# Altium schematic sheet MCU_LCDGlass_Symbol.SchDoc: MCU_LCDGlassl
size A3; DocumentNumber: MB1144; Revision: C-02; SheetNumber: 2; SheetTotal: 25; PageSetup: Record=PageOptions|CenterHorizontal=True|CenterVertical=True|PrintScale=1.01|XCorrection=1.00|YCorrection=1.00|PrintKind=1|BorderSize=5000000|LeftOffset=0|BottomOffset=0|Orientation=2|PaperLength=1000|PaperWidth=1000|Scale=100|PaperSource=264|PrintQuality=600|MediaType=1|DitherType=10|PaperKind=A3|PrintScaleMode=1; Project: STM32L476G-EVAL
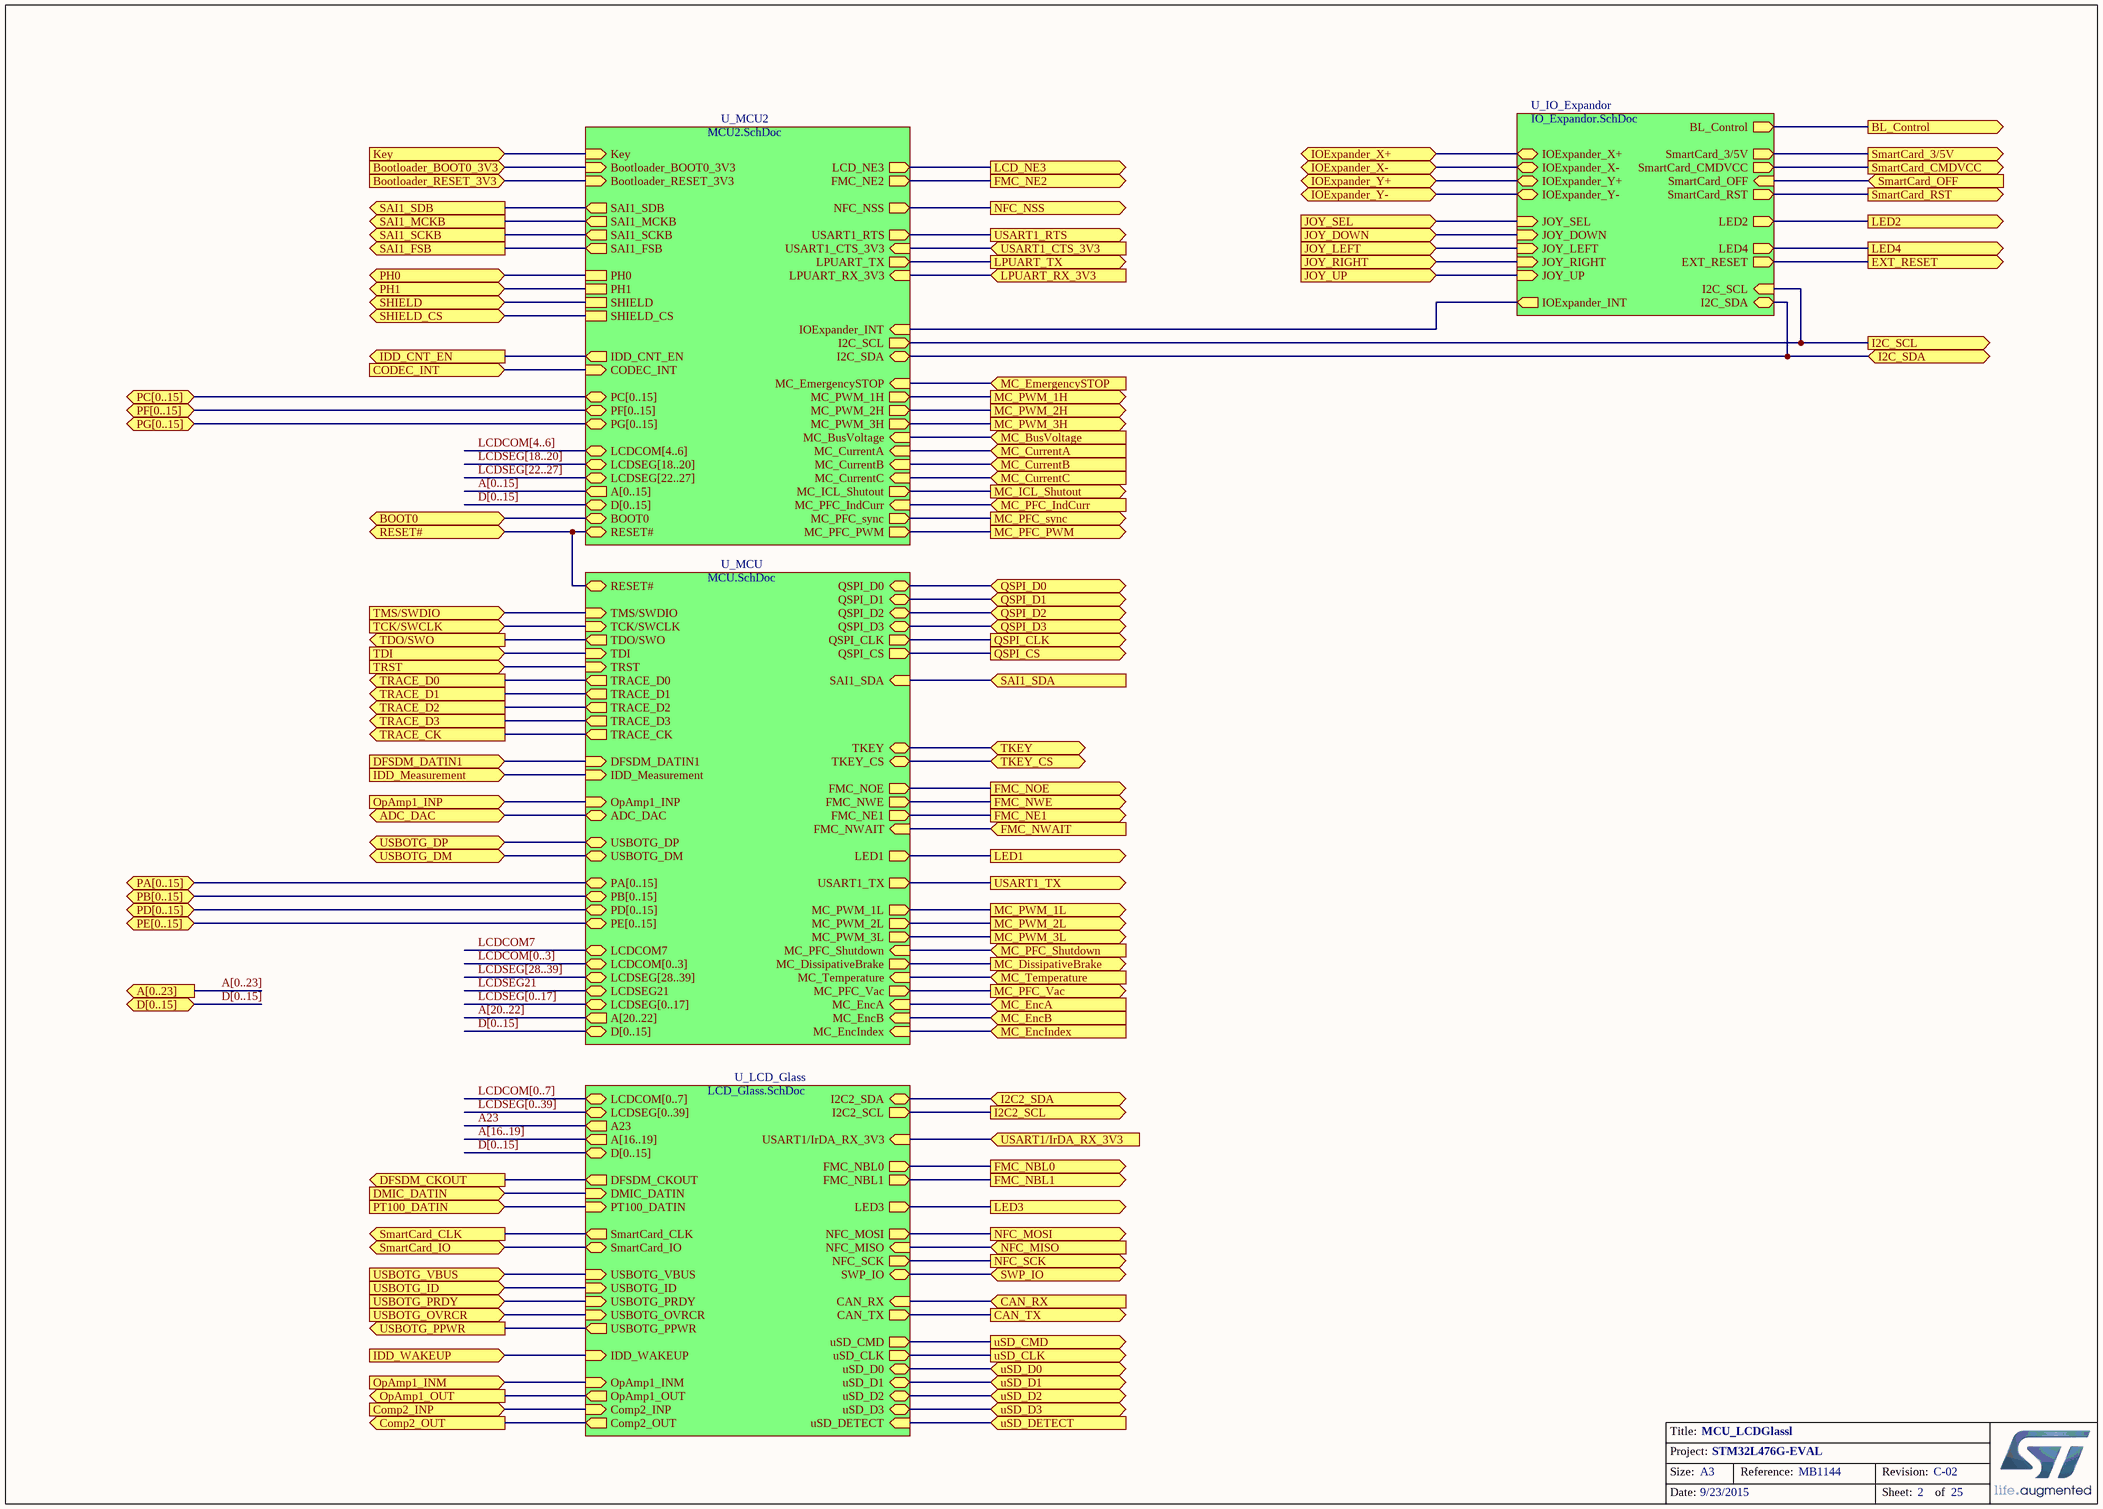
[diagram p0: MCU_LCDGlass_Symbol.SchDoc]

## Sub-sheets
U_IO_Expandor = IO_Expandor.SchDoc: IOExpander_Y+ (bidir), IOExpander_Y- (bidir), IOExpander_X+ (bidir), IOExpander_X- (bidir), IOExpander_INT (out), I2C_SDA (bidir), JOY_SEL (in), JOY_DOWN (in), JOY_LEFT (in), JOY_RIGHT (in), JOY_UP (in), LED4 (out), SmartCard_RST (out), SmartCard_CMDVCC (out), SmartCard_3/5V (out), SmartCard_OFF (in), I2C_SCL (in), LED2 (out), BL_Control (out), EXT_RESET (out)
U_LCD_Glass = LCD_Glass.SchDoc: uSD_CMD (out), uSD_CLK (out), uSD_D3 (bidir), uSD_D2 (bidir), IDD_WAKEUP (in), PT100_DATIN (in), uSD_D0 (bidir), uSD_D1 (bidir), OpAmp1_INM (in), FMC_NBL0 (out), FMC_NBL1 (out), LCDSEG[0..39] (bidir), LCDCOM[0..7] (bidir), USBOTG_VBUS (in), USBOTG_ID (in), CAN_TX (out), SWP_IO (bidir), CAN_RX (in), DMIC_DATIN (in), OpAmp1_OUT (out), Comp2_INP (in), SmartCard_CLK (out), SmartCard_IO (bidir), uSD_DETECT (in), DFSDM_CKOUT (out), D[0..15] (bidir), USBOTG_PRDY (in), USBOTG_OVRCR (in), USBOTG_PPWR (out), Comp2_OUT (out), USART1/IrDA_RX_3V3 (in), A[16..19] (out), A23 (out), NFC_MISO (in), NFC_SCK (out), NFC_MOSI (out), I2C2_SDA (bidir), I2C2_SCL (out), LED3 (out)
U_MCU = MCU.SchDoc: PA[0..15] (bidir), PB[0..15] (bidir), PD[0..15] (bidir), PE[0..15] (bidir), USBOTG_DM (bidir), USBOTG_DP (bidir), TMS/SWDIO (in), TCK/SWCLK (in), DFSDM_DATIN1 (in), FMC_NOE (out), FMC_NWE (out), FMC_NWAIT (in), FMC_NE1 (out), TRACE_D3 (out), TRACE_D1 (out), TRST (in), D[0..15] (bidir), IDD_Measurement (in), USART1_TX (out), LED1 (out), MC_DissipativeBrake (out), TRACE_D2 (out), MC_EncA (in), TDI (in), TDO/SWO (out), ADC_DAC (bidir), RESET# (bidir), QSPI_D3 (bidir), QSPI_D2 (bidir), QSPI_D1 (bidir), QSPI_D0 (bidir), QSPI_CLK (out), QSPI_CS (out), TRACE_D0 (out), TRACE_CK (out), SAI1_SDA (in), OpAmp1_INP (in), MC_PFC_Vac (out), MC_Temperature (in), MC_EncB (in), MC_EncIndex (in), TKEY, TKEY_CS, MC_PWM_1L (out), MC_PWM_2L (out), MC_PWM_3L (out), MC_PFC_Shutdown (in), A[20..22] (out), LCDCOM[0..3] (bidir), LCDCOM7, LCDSEG[0..17] (bidir), LCDSEG[28..39] (bidir), LCDSEG21 (bidir)
U_MCU2 = MCU2.SchDoc: PC[0..15] (bidir), Bootloader_BOOT0_3V3 (in), Bootloader_RESET_3V3 (in), Key (in), CODEC_INT (in), USART1_CTS_3V3 (in), FMC_NE2 (out), USART1_RTS (out), PF[0..15] (bidir), PG[0..15] (bidir), D[0..15] (bidir), MC_PFC_sync (out), IDD_CNT_EN (out), LPUART_TX (out), LPUART_RX_3V3 (in), LCD_NE3 (out), IOExpander_INT (in), I2C_SCL (out), I2C_SDA (bidir), RESET# (bidir), PH1, PH0, SHIELD, SAI1_SDB (out), SAI1_MCKB (out), SAI1_SCKB (out), SAI1_FSB (out), MC_ICL_Shutout (out), MC_PFC_PWM (out), MC_CurrentB (in), MC_CurrentC (in), MC_CurrentA (in), MC_PFC_IndCurr (in), MC_BusVoltage (in), MC_PWM_1H (out), SHIELD_CS, MC_PWM_2H (out), MC_PWM_3H (out), MC_EmergencySTOP (in), A[0..15] (out), LCDSEG[18..20] (bidir), LCDCOM[4..6] (bidir), LCDSEG[22..27] (bidir), BOOT0, NFC_NSS (out)

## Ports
A[0..23] (out), ADC_DAC (bidir), BL_Control (out), BOOT0, Bootloader_BOOT0_3V3 (in), Bootloader_RESET_3V3 (in), CAN_RX (in), CAN_TX (out), CODEC_INT (in), Comp2_INP (in), Comp2_OUT (out), D[0..15] (bidir), DFSDM_CKOUT (out), DFSDM_DATIN1 (in), DMIC_DATIN (in), EXT_RESET (out), FMC_NBL0 (out), FMC_NBL1 (out), FMC_NE1 (out), FMC_NE2 (out), FMC_NOE (out), FMC_NWAIT (in), FMC_NWE (out), I2C2_SCL (out), I2C2_SDA (bidir), I2C_SCL (out), I2C_SDA (bidir), IDD_CNT_EN (out), IDD_Measurement (in), IDD_WAKEUP (in), IOExpander_X+ (bidir), IOExpander_X- (bidir), IOExpander_Y+ (bidir), IOExpander_Y- (bidir), JOY_DOWN (in), JOY_LEFT (in), JOY_RIGHT (in), JOY_SEL (in), JOY_UP (in), Key (in), LCD_NE3 (out), LED1 (out), LED2 (out), LED3 (out), LED4 (out), LPUART_RX_3V3 (in), LPUART_TX (out), MC_BusVoltage (in), MC_CurrentA (in), MC_CurrentB (in), MC_CurrentC (in), MC_DissipativeBrake (out), MC_EmergencySTOP (in), MC_EncA (in), MC_EncB (in), MC_EncIndex (in), MC_ICL_Shutout (out), MC_PFC_IndCurr (in), MC_PFC_PWM (out), MC_PFC_Shutdown (in), MC_PFC_sync (out), MC_PFC_Vac (out), MC_PWM_1H (out), MC_PWM_1L (out), MC_PWM_2H (out), MC_PWM_2L (out), MC_PWM_3H (out), MC_PWM_3L (out), MC_Temperature (in), NFC_MISO (in), NFC_MOSI (out), NFC_NSS (out), NFC_SCK (out), OpAmp1_INM (in), OpAmp1_INP (in), OpAmp1_OUT (out), PA[0..15] (bidir), PB[0..15] (bidir), PC[0..15] (bidir), PD[0..15] (bidir), PE[0..15] (bidir), PF[0..15] (bidir), PG[0..15] (bidir), PH0, PH1, PT100_DATIN (in), QSPI_CLK (out), QSPI_CS (out), QSPI_D0 (bidir), QSPI_D1 (bidir), QSPI_D2 (bidir), QSPI_D3 (bidir), RESET# (bidir), SAI1_FSB (out), SAI1_MCKB (out), SAI1_SCKB (out), SAI1_SDA (in), SAI1_SDB (out), SHIELD, SHIELD_CS, SmartCard_3/5V (out), SmartCard_CLK (out), SmartCard_CMDVCC (out), SmartCard_IO (bidir), SmartCard_OFF (in), SmartCard_RST (out), SWP_IO (bidir), TCK/SWCLK (in), TDI (in), TDO/SWO (out), TKEY, TKEY_CS, TMS/SWDIO (in), TRACE_CK (out), TRACE_D0 (out), TRACE_D1 (out), TRACE_D2 (out), TRACE_D3 (out), TRST (in), USART1/IrDA_RX_3V3 (in), USART1_CTS_3V3 (in), USART1_RTS (out), USART1_TX (out), USBOTG_DM (bidir), USBOTG_DP (bidir), USBOTG_ID (in), USBOTG_OVRCR (in), USBOTG_PPWR (out), USBOTG_PRDY (in), USBOTG_VBUS (in), uSD_CLK (out), uSD_CMD (out), uSD_D0 (bidir), uSD_D1 (bidir), uSD_D2 (bidir), uSD_D3 (bidir), uSD_DETECT (in)

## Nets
ADC_DAC: port ADC_DAC, sheet U_MCU/ADC_DAC
BL_Control: port BL_Control, sheet U_IO_Expandor/BL_Control
BOOT0: port BOOT0, sheet U_MCU2/BOOT0
Bootloader_BOOT0_3V3: port Bootloader_BOOT0_3V3, sheet U_MCU2/Bootloader_BOOT0_3V3
Bootloader_RESET_3V3: port Bootloader_RESET_3V3, sheet U_MCU2/Bootloader_RESET_3V3
CAN_RX: port CAN_RX, sheet U_LCD_Glass/CAN_RX
CAN_TX: port CAN_TX, sheet U_LCD_Glass/CAN_TX
CODEC_INT: port CODEC_INT, sheet U_MCU2/CODEC_INT
Comp2_INP: port Comp2_INP, sheet U_LCD_Glass/Comp2_INP
Comp2_OUT: port Comp2_OUT, sheet U_LCD_Glass/Comp2_OUT
DFSDM_CKOUT: port DFSDM_CKOUT, sheet U_LCD_Glass/DFSDM_CKOUT
DFSDM_DATIN1: port DFSDM_DATIN1, sheet U_MCU/DFSDM_DATIN1
DMIC_DATIN: port DMIC_DATIN, sheet U_LCD_Glass/DMIC_DATIN
EXT_RESET: port EXT_RESET, sheet U_IO_Expandor/EXT_RESET
FMC_NBL0: port FMC_NBL0, sheet U_LCD_Glass/FMC_NBL0
FMC_NBL1: port FMC_NBL1, sheet U_LCD_Glass/FMC_NBL1
FMC_NE1: port FMC_NE1, sheet U_MCU/FMC_NE1
FMC_NE2: port FMC_NE2, sheet U_MCU2/FMC_NE2
FMC_NOE: port FMC_NOE, sheet U_MCU/FMC_NOE
FMC_NWAIT: port FMC_NWAIT, sheet U_MCU/FMC_NWAIT
FMC_NWE: port FMC_NWE, sheet U_MCU/FMC_NWE
I2C2_SCL: port I2C2_SCL, sheet U_LCD_Glass/I2C2_SCL
I2C2_SDA: port I2C2_SDA, sheet U_LCD_Glass/I2C2_SDA
I2C_SCL: port I2C_SCL, sheet U_IO_Expandor/I2C_SCL, sheet U_MCU2/I2C_SCL
I2C_SDA: port I2C_SDA, sheet U_IO_Expandor/I2C_SDA, sheet U_MCU2/I2C_SDA
IDD_CNT_EN: port IDD_CNT_EN, sheet U_MCU2/IDD_CNT_EN
IDD_Measurement: port IDD_Measurement, sheet U_MCU/IDD_Measurement
IDD_WAKEUP: port IDD_WAKEUP, sheet U_LCD_Glass/IDD_WAKEUP
IOExpander_X+: port IOExpander_X+, sheet U_IO_Expandor/IOExpander_X+
IOExpander_X-: port IOExpander_X-, sheet U_IO_Expandor/IOExpander_X-
IOExpander_Y+: port IOExpander_Y+, sheet U_IO_Expandor/IOExpander_Y+
IOExpander_Y-: port IOExpander_Y-, sheet U_IO_Expandor/IOExpander_Y-
JOY_DOWN: port JOY_DOWN, sheet U_IO_Expandor/JOY_DOWN
JOY_LEFT: port JOY_LEFT, sheet U_IO_Expandor/JOY_LEFT
JOY_RIGHT: port JOY_RIGHT, sheet U_IO_Expandor/JOY_RIGHT
JOY_SEL: port JOY_SEL, sheet U_IO_Expandor/JOY_SEL
JOY_UP: port JOY_UP, sheet U_IO_Expandor/JOY_UP
Key: port Key, sheet U_MCU2/Key
LCD_NE3: port LCD_NE3, sheet U_MCU2/LCD_NE3
LED1: port LED1, sheet U_MCU/LED1
LED2: port LED2, sheet U_IO_Expandor/LED2
LED3: port LED3, sheet U_LCD_Glass/LED3
LED4: port LED4, sheet U_IO_Expandor/LED4
LPUART_RX_3V3: port LPUART_RX_3V3, sheet U_MCU2/LPUART_RX_3V3
LPUART_TX: port LPUART_TX, sheet U_MCU2/LPUART_TX
MC_BusVoltage: port MC_BusVoltage, sheet U_MCU2/MC_BusVoltage
MC_CurrentA: port MC_CurrentA, sheet U_MCU2/MC_CurrentA
MC_CurrentB: port MC_CurrentB, sheet U_MCU2/MC_CurrentB
MC_CurrentC: port MC_CurrentC, sheet U_MCU2/MC_CurrentC
MC_DissipativeBrake: port MC_DissipativeBrake, sheet U_MCU/MC_DissipativeBrake
MC_EmergencySTOP: port MC_EmergencySTOP, sheet U_MCU2/MC_EmergencySTOP
MC_EncA: port MC_EncA, sheet U_MCU/MC_EncA
MC_EncB: port MC_EncB, sheet U_MCU/MC_EncB
MC_EncIndex: port MC_EncIndex, sheet U_MCU/MC_EncIndex
MC_ICL_Shutout: port MC_ICL_Shutout, sheet U_MCU2/MC_ICL_Shutout
MC_PFC_IndCurr: port MC_PFC_IndCurr, sheet U_MCU2/MC_PFC_IndCurr
MC_PFC_PWM: port MC_PFC_PWM, sheet U_MCU2/MC_PFC_PWM
MC_PFC_Shutdown: port MC_PFC_Shutdown, sheet U_MCU/MC_PFC_Shutdown
MC_PFC_sync: port MC_PFC_sync, sheet U_MCU2/MC_PFC_sync
MC_PFC_Vac: port MC_PFC_Vac, sheet U_MCU/MC_PFC_Vac
MC_PWM_1H: port MC_PWM_1H, sheet U_MCU2/MC_PWM_1H
MC_PWM_1L: port MC_PWM_1L, sheet U_MCU/MC_PWM_1L
MC_PWM_2H: port MC_PWM_2H, sheet U_MCU2/MC_PWM_2H
MC_PWM_2L: port MC_PWM_2L, sheet U_MCU/MC_PWM_2L
MC_PWM_3H: port MC_PWM_3H, sheet U_MCU2/MC_PWM_3H
MC_PWM_3L: port MC_PWM_3L, sheet U_MCU/MC_PWM_3L
MC_Temperature: port MC_Temperature, sheet U_MCU/MC_Temperature
NFC_MISO: port NFC_MISO, sheet U_LCD_Glass/NFC_MISO
NFC_MOSI: port NFC_MOSI, sheet U_LCD_Glass/NFC_MOSI
NFC_NSS: port NFC_NSS, sheet U_MCU2/NFC_NSS
NFC_SCK: port NFC_SCK, sheet U_LCD_Glass/NFC_SCK
OpAmp1_INM: port OpAmp1_INM, sheet U_LCD_Glass/OpAmp1_INM
OpAmp1_INP: port OpAmp1_INP, sheet U_MCU/OpAmp1_INP
OpAmp1_OUT: port OpAmp1_OUT, sheet U_LCD_Glass/OpAmp1_OUT
PH0: port PH0, sheet U_MCU2/PH0
PH1: port PH1, sheet U_MCU2/PH1
PT100_DATIN: port PT100_DATIN, sheet U_LCD_Glass/PT100_DATIN
QSPI_CLK: port QSPI_CLK, sheet U_MCU/QSPI_CLK
QSPI_CS: port QSPI_CS, sheet U_MCU/QSPI_CS
QSPI_D0: port QSPI_D0, sheet U_MCU/QSPI_D0
QSPI_D1: port QSPI_D1, sheet U_MCU/QSPI_D1
QSPI_D2: port QSPI_D2, sheet U_MCU/QSPI_D2
QSPI_D3: port QSPI_D3, sheet U_MCU/QSPI_D3
RESET#: port RESET#, sheet U_MCU/RESET#, sheet U_MCU2/RESET#
SAI1_FSB: port SAI1_FSB, sheet U_MCU2/SAI1_FSB
SAI1_MCKB: port SAI1_MCKB, sheet U_MCU2/SAI1_MCKB
SAI1_SCKB: port SAI1_SCKB, sheet U_MCU2/SAI1_SCKB
SAI1_SDA: port SAI1_SDA, sheet U_MCU/SAI1_SDA
SAI1_SDB: port SAI1_SDB, sheet U_MCU2/SAI1_SDB
SHIELD: port SHIELD, sheet U_MCU2/SHIELD
SHIELD_CS: port SHIELD_CS, sheet U_MCU2/SHIELD_CS
SmartCard_3/5V: port SmartCard_3/5V, sheet U_IO_Expandor/SmartCard_3/5V
SmartCard_CLK: port SmartCard_CLK, sheet U_LCD_Glass/SmartCard_CLK
SmartCard_CMDVCC: port SmartCard_CMDVCC, sheet U_IO_Expandor/SmartCard_CMDVCC
SmartCard_IO: port SmartCard_IO, sheet U_LCD_Glass/SmartCard_IO
SmartCard_OFF: port SmartCard_OFF, sheet U_IO_Expandor/SmartCard_OFF
SmartCard_RST: port SmartCard_RST, sheet U_IO_Expandor/SmartCard_RST
SWP_IO: port SWP_IO, sheet U_LCD_Glass/SWP_IO
TCK/SWCLK: port TCK/SWCLK, sheet U_MCU/TCK/SWCLK
TDI: port TDI, sheet U_MCU/TDI
TDO/SWO: port TDO/SWO, sheet U_MCU/TDO/SWO
TKEY: port TKEY, sheet U_MCU/TKEY
TKEY_CS: port TKEY_CS, sheet U_MCU/TKEY_CS
TMS/SWDIO: port TMS/SWDIO, sheet U_MCU/TMS/SWDIO
TRACE_CK: port TRACE_CK, sheet U_MCU/TRACE_CK
TRACE_D0: port TRACE_D0, sheet U_MCU/TRACE_D0
TRACE_D1: port TRACE_D1, sheet U_MCU/TRACE_D1
TRACE_D2: port TRACE_D2, sheet U_MCU/TRACE_D2
TRACE_D3: port TRACE_D3, sheet U_MCU/TRACE_D3
TRST: port TRST, sheet U_MCU/TRST
USART1/IrDA_RX_3V3: port USART1/IrDA_RX_3V3, sheet U_LCD_Glass/USART1/IrDA_RX_3V3
USART1_CTS_3V3: port USART1_CTS_3V3, sheet U_MCU2/USART1_CTS_3V3
USART1_RTS: port USART1_RTS, sheet U_MCU2/USART1_RTS
USART1_TX: port USART1_TX, sheet U_MCU/USART1_TX
USBOTG_DM: port USBOTG_DM, sheet U_MCU/USBOTG_DM
USBOTG_DP: port USBOTG_DP, sheet U_MCU/USBOTG_DP
USBOTG_ID: port USBOTG_ID, sheet U_LCD_Glass/USBOTG_ID
USBOTG_OVRCR: port USBOTG_OVRCR, sheet U_LCD_Glass/USBOTG_OVRCR
USBOTG_PPWR: port USBOTG_PPWR, sheet U_LCD_Glass/USBOTG_PPWR
USBOTG_PRDY: port USBOTG_PRDY, sheet U_LCD_Glass/USBOTG_PRDY
USBOTG_VBUS: port USBOTG_VBUS, sheet U_LCD_Glass/USBOTG_VBUS
uSD_CLK: port uSD_CLK, sheet U_LCD_Glass/uSD_CLK
uSD_CMD: port uSD_CMD, sheet U_LCD_Glass/uSD_CMD
uSD_D0: port uSD_D0, sheet U_LCD_Glass/uSD_D0
uSD_D1: port uSD_D1, sheet U_LCD_Glass/uSD_D1
uSD_D2: port uSD_D2, sheet U_LCD_Glass/uSD_D2
uSD_D3: port uSD_D3, sheet U_LCD_Glass/uSD_D3
uSD_DETECT: port uSD_DETECT, sheet U_LCD_Glass/uSD_DETECT
(unnamed): sheet U_IO_Expandor/IOExpander_INT, sheet U_MCU2/IOExpander_INT

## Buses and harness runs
bus A[0..15] = sheet U_MCU2/A[0..15]
bus A[0..23] = port A[0..23]
bus A[16..19] = sheet U_LCD_Glass/A[16..19]
bus A[20..22] = sheet U_MCU/A[20..22]
bus D[0..15] = port D[0..15]
bus D[0..15] = sheet U_LCD_Glass/D[0..15]
bus D[0..15] = sheet U_MCU2/D[0..15]
bus D[0..15] = sheet U_MCU/D[0..15]
bus LCDCOM[0..3] = sheet U_MCU/LCDCOM[0..3]
bus LCDCOM[0..7] = sheet U_LCD_Glass/LCDCOM[0..7]
bus LCDCOM[4..6] = sheet U_MCU2/LCDCOM[4..6]
bus LCDSEG[0..17] = sheet U_MCU/LCDSEG[0..17]
bus LCDSEG[0..39] = sheet U_LCD_Glass/LCDSEG[0..39]
bus LCDSEG[18..20] = sheet U_MCU2/LCDSEG[18..20]
bus LCDSEG[22..27] = sheet U_MCU2/LCDSEG[22..27]
bus LCDSEG[28..39] = sheet U_MCU/LCDSEG[28..39]
bus port PA[0..15] = sheet U_MCU/PA[0..15]
bus port PB[0..15] = sheet U_MCU/PB[0..15]
bus port PC[0..15] = sheet U_MCU2/PC[0..15]
bus port PD[0..15] = sheet U_MCU/PD[0..15]
bus port PE[0..15] = sheet U_MCU/PE[0..15]
bus port PF[0..15] = sheet U_MCU2/PF[0..15]
bus port PG[0..15] = sheet U_MCU2/PG[0..15]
